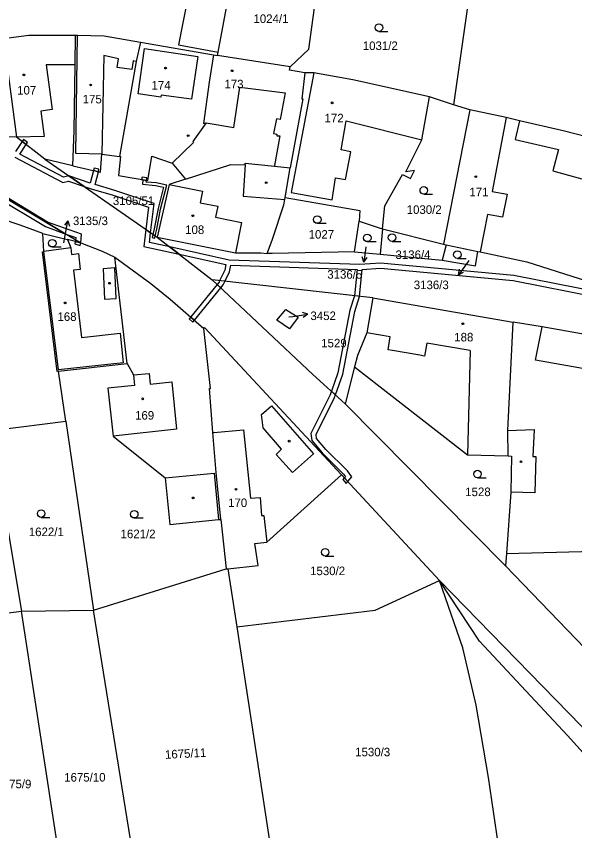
# Model space of a CAD drawing. Extents: x -776734 to -748832, y -1118122 to -976986.
# Drawn here: x -752860 to -752749.1, y -1115826.7 to -1115665 of the extents above; entities that cross this region are included whole.
import ezdxf

# ---------------------------------------------------------------- set-up
doc = ezdxf.new("R2010")
doc.units = 0
for name, color, linetype in [('KM_Hranice parcel', 7, 'Continuous'), ('KM_Parcelní čísla', 7, 'Continuous'), ('KM_Pop  PČ popisy', 7, 'Continuous'), ('KM_Vnitřní kresba', 7, 'Continuous'), ('KM_Věcná břemena k části', 7, 'Continuous'), ('KM_Značky budov', 7, 'Continuous'), ('KM_Značky kultur', 7, 'Continuous')]:
    doc.layers.add(name, color=color, linetype=linetype)

msp = doc.modelspace()

# ---------------------------------------------------------------- linework, layer by layer
at = {"layer": 'KM_Hranice parcel'}
for p, q in [((-752770.11, -1115661.14), (-752773.14, -1115682.57)), ((-752862.57, -1115669.36), (-752859.94, -1115688.99)), ((-752835.31, -1115670.11), (-752820.81, -1115672.62)), ((-752820.81, -1115672.62), (-752820.03, -1115672.75)), ((-752805.59, -1115675.01), (-752820.03, -1115672.75)), ((-752773.14, -1115682.57), (-752777.95, -1115680.94)), ((-752769.92, -1115683.54), (-752773.14, -1115682.57)), ((-752769.92, -1115683.54), (-752775.13, -1115710.23)), ((-752859.94, -1115688.99), (-752868.36, -1115688.71)), ((-752854.31, -1115693.32), (-752859.94, -1115688.99)), ((-752848.8, -1115694.67), (-752854.31, -1115693.32)), ((-752854.31, -1115693.32), (-752832.01, -1115708.85)), ((-752829.01, -1115694.11), (-752826.41, -1115697.32)), ((-752806.62, -1115700.96), (-752805.58, -1115695.03)), ((-752870.06, -1115696.32), (-752847.19, -1115709.96)), ((-752806.62, -1115700.96), (-752791.76, -1115703.53)), ((-752791.76, -1115703.53), (-752791.9, -1115705.62)), ((-752792.8, -1115711.7), (-752791.9, -1115705.62)), ((-752854.54, -1115711.68), (-752854.76, -1115708.06)), ((-752854.76, -1115708.06), (-752849.81, -1115709.31)), ((-752787.25, -1115707.18), (-752787.75, -1115712.18)), ((-752787.25, -1115707.18), (-752775.13, -1115710.23)), ((-752847.19, -1115709.96), (-752849.81, -1115709.31)), ((-752832.01, -1115708.85), (-752821.07, -1115717.32)), ((-752774.64, -1115710.33), (-752775.42, -1115713.37)), ((-752775.13, -1115710.23), (-752774.64, -1115710.33)), ((-752774.64, -1115710.33), (-752768.29, -1115711.67)), ((-752792.8, -1115711.7), (-752787.75, -1115712.18)), ((-752838, -1115733.9), (-752840.43, -1115712.78)), ((-752787.75, -1115712.18), (-752775.42, -1115713.37)), ((-752789.16, -1115720.89), (-752821.07, -1115717.32)), ((-752789.16, -1115720.89), (-752761.29, -1115725.71)), ((-752851.61, -1115735.44), (-752838, -1115733.9)), ((-752792.81, -1115734.59), (-752794.65, -1115741.88)), ((-752850.16, -1115745.33), (-752851.61, -1115735.44)), ((-752762.79, -1115774.11), (-752794.65, -1115741.88)), ((-752864.92, -1115747.25), (-752850.16, -1115745.33)), ((-752850.16, -1115745.33), (-752844.67, -1115782.9)), ((-752864.37, -1115751.01), (-752858.96, -1115783.05)), ((-752795.39, -1115755.98), (-752775.93, -1115776.97)), ((-752819.34, -1115764.85), (-752818.29, -1115774.68)), ((-752762.62, -1115771.65), (-752762.79, -1115774.11)), ((-752762.62, -1115771.65), (-752741.18, -1115771.07)), ((-752844.67, -1115782.9), (-752818.29, -1115774.68)), ((-752818.29, -1115774.68), (-752818, -1115774.65)), ((-752818, -1115774.65), (-752816.22, -1115786.21)), ((-752729.95, -1115808.28), (-752762.79, -1115774.11)), ((-752873.85, -1115785.05), (-752858.96, -1115783.05)), ((-752858.96, -1115783.05), (-752844.67, -1115782.9)), ((-752848.25, -1115852.83), (-752858.96, -1115783.05)), ((-752833.78, -1115850.14), (-752844.67, -1115782.9)), ((-752816.22, -1115786.21), (-752807.07, -1115845.79))]:
    msp.add_line(p, q, dxfattribs=at)
for points in [[(-752820.03, -1115672.75), (-752819.9, -1115672.08), (-752816.31, -1115652.88), (-752815.97, -1115650.74)], [(-752805.59, -1115675.01), (-752801.91, -1115671.5), (-752799.51, -1115654.01)], [(-752862.57, -1115669.36), (-752857.51, -1115668.7), (-752848.27, -1115668.68)], [(-752848.8, -1115694.67), (-752848.51, -1115687.63), (-752848.29, -1115674.57), (-752848.27, -1115668.68)], [(-752848.27, -1115668.68), (-752847.82, -1115668.69), (-752842.52, -1115668.84), (-752835.31, -1115670.11)], [(-752835.31, -1115670.11), (-752836.22, -1115673.92), (-752839.23, -1115691.3), (-752839.49, -1115692.79)], [(-752820.81, -1115672.62), (-752821.72, -1115678.02), (-752822.8, -1115686.25), (-752822.29, -1115686.12), (-752824.91, -1115689.79), (-752824.79, -1115690), (-752829.01, -1115694.11)], [(-752802.71, -1115676.22), (-752805.76, -1115675.67), (-752805.59, -1115675.01)], [(-752802.71, -1115676.22), (-752803.3, -1115681.33), (-752803.07, -1115681.37), (-752805.58, -1115695.03)], [(-752777.95, -1115680.94), (-752793.12, -1115677.57), (-752800.89, -1115676.17), (-752802.71, -1115676.22)], [(-752787.25, -1115707.18), (-752786.78, -1115702.59), (-752783.3, -1115696.36), (-752781.72, -1115697.14), (-752780.9, -1115695.57), (-752782.64, -1115695.83), (-752779.42, -1115689.51), (-752777.95, -1115680.94)], [(-752719.2, -1115696.43), (-752725.51, -1115694.41), (-752737.47, -1115691.3), (-752751.34, -1115687.73), (-752760.01, -1115685.71), (-752762.66, -1115685.09), (-752769.92, -1115683.54)], [(-752848.8, -1115694.67), (-752843.25, -1115695.92), (-752843.02, -1115692.33), (-752839.49, -1115692.79)], [(-752839.49, -1115692.79), (-752839.32, -1115692.81), (-752839.67, -1115696.59), (-752833.89, -1115697.59), (-752833.09, -1115692.74), (-752829.01, -1115694.11)], [(-752826.41, -1115697.32), (-752817.38, -1115694.37), (-752814.57, -1115694.44), (-752814.55, -1115694.14), (-752808.72, -1115694.72), (-752805.58, -1115695.03)], [(-752826.41, -1115697.32), (-752829.63, -1115698.33), (-752832.01, -1115708.85)], [(-752810.18, -1115712.03), (-752809.14, -1115709.22), (-752806.87, -1115702.43), (-752806.68, -1115701.33), (-752806.62, -1115700.96)], [(-752854.76, -1115708.06), (-752859.26, -1115706.43), (-752863.17, -1115705.14), (-752864.66, -1115704.88)], [(-752791.9, -1115705.62), (-752787.73, -1115707.05), (-752787.25, -1115707.18)], [(-752849.81, -1115709.31), (-752849.18, -1115710.96), (-752854.54, -1115711.68)], [(-752847.19, -1115709.96), (-752842.94, -1115711.59), (-752840.43, -1115712.78)], [(-752832.01, -1115708.85), (-752816.46, -1115711.91), (-752811.41, -1115711.95), (-752810.18, -1115712.03)], [(-752851.61, -1115735.44), (-752851.91, -1115735.47), (-752854.83, -1115711.72), (-752854.54, -1115711.68)], [(-752792.8, -1115711.7), (-752809.19, -1115712.09), (-752810.18, -1115712.03)], [(-752775.42, -1115713.37), (-752768.78, -1115714.51), (-752768.29, -1115711.67)], [(-752768.29, -1115711.67), (-752767.84, -1115711.76), (-752758.58, -1115713.72), (-752746.7, -1115717.52), (-752736.61, -1115720.55), (-752727.86, -1115722.24)], [(-752840.43, -1115712.78), (-752833.26, -1115718), (-752829.45, -1115721.1), (-752822.74, -1115726.96)], [(-752794.65, -1115741.88), (-752801.11, -1115736.06), (-752821.07, -1115717.32)], [(-752789.16, -1115720.89), (-752790.38, -1115727.84), (-752792.23, -1115732.29), (-752792.81, -1115734.59)], [(-752806.46, -1115723.16), (-752804, -1115724.71), (-752805.7, -1115727.03), (-752808.22, -1115725.31), (-752806.46, -1115723.16)], [(-752762.28, -1115752.26), (-752762.35, -1115747.19), (-752761.29, -1115725.71)], [(-752732.48, -1115730.75), (-752755.56, -1115726.65), (-752761.29, -1115725.71)], [(-752822.74, -1115726.96), (-752822.62, -1115726.73), (-752795.39, -1115755.98)], [(-752819.34, -1115764.85), (-752820.33, -1115755.58), (-752820.95, -1115747.63), (-752821.63, -1115738.88), (-752821.44, -1115738.86), (-752822.74, -1115726.96)], [(-752838, -1115733.9), (-752836.75, -1115736.17), (-752836.54, -1115738.29), (-752841.83, -1115738.81), (-752840.78, -1115748.33), (-752830.42, -1115756.6), (-752829.53, -1115765.85), (-752819.83, -1115764.9), (-752819.34, -1115764.85)], [(-752792.81, -1115734.59), (-752770.36, -1115752.06), (-752762.28, -1115752.26)], [(-752762.28, -1115752.26), (-752761.66, -1115752.28), (-752761.77, -1115759.47), (-752762.62, -1115771.65)], [(-752818, -1115774.65), (-752811.98, -1115774.01), (-752812.59, -1115769.65), (-752810.26, -1115769.4), (-752795.39, -1115755.98)], [(-752816.22, -1115786.21), (-752788.74, -1115782.85), (-752775.93, -1115776.97)], [(-752736.32, -1115823.45), (-752750.53, -1115807.77), (-752767.96, -1115789.02), (-752775.93, -1115776.97)], [(-752762.91, -1115838.6), (-752766.17, -1115816.08), (-752768.64, -1115801.76), (-752771.29, -1115790.38), (-752775.93, -1115776.97)], [(-752775.93, -1115776.97), (-752724.69, -1115829.55), (-752661.99, -1115897.03)]]:
    msp.add_lwpolyline(points, dxfattribs=at)
at = {"layer": 'KM_Pop  PČ popisy'}
for p, q in [((-752849.779, -1115705.565), (-752850.446, -1115706.464)), ((-752850.3, -1115708.52), (-752849.779, -1115705.565)), ((-752849.779, -1115705.565), (-752849.46, -1115706.638)), ((-752850.56, -1115709.95), (-752850.3, -1115708.52)), ((-752790.57, -1115710.83), (-752790.936, -1115713.809)), ((-752790.56, -1115710.75), (-752790.57, -1115710.83)), ((-752790.936, -1115713.809), (-752791.311, -1115712.754)), ((-752790.936, -1115713.809), (-752790.317, -1115712.876)), ((-752770.08, -1115713.46), (-752770.38, -1115713.87)), ((-752770.38, -1115713.87), (-752772.144, -1115716.298)), ((-752772.144, -1115716.298), (-752771.96, -1115715.193)), ((-752772.144, -1115716.298), (-752771.15, -1115715.782)), ((-752805.89, -1115724.67), (-752805.09, -1115724.55)), ((-752805.09, -1115724.55), (-752802.118, -1115724.132)), ((-752802.118, -1115724.132), (-752803.18, -1115723.776)), ((-752802.118, -1115724.132), (-752803.04, -1115724.768))]:
    msp.add_line(p, q, dxfattribs=at)
at = {"layer": 'KM_Vnitřní kresba'}
for p, q in [((-752824.01, -1115651.39), (-752827.78, -1115670.61)), ((-752848.15, -1115692.22), (-752847.82, -1115668.69)), ((-752835.82, -1115680.38), (-752834.51, -1115671.36)), ((-752834.51, -1115671.36), (-752823.92, -1115672.93)), ((-752827.78, -1115670.61), (-752819.9, -1115672.08)), ((-752842.62, -1115672.72), (-752843.02, -1115692.33)), ((-752839.71, -1115673.39), (-752842.62, -1115672.72)), ((-752823.92, -1115672.93), (-752825.18, -1115681.43)), ((-752848.29, -1115674.57), (-752854.09, -1115674.63)), ((-752854.09, -1115674.63), (-752852.91, -1115683.48)), ((-752839.96, -1115675.11), (-752839.71, -1115673.39)), ((-752836.81, -1115673.83), (-752837.06, -1115675.53)), ((-752836.22, -1115673.92), (-752836.81, -1115673.83)), ((-752837.06, -1115675.53), (-752839.96, -1115675.11)), ((-752800.89, -1115676.17), (-752805.4, -1115699.93)), ((-752816.79, -1115687.06), (-752815.61, -1115679.02)), ((-752815.61, -1115679.02), (-752806.62, -1115680.14)), ((-752831.31, -1115681.04), (-752835.82, -1115680.38)), ((-752831.24, -1115680.59), (-752831.31, -1115681.04)), ((-752825.18, -1115681.43), (-752831.24, -1115680.59)), ((-752806.62, -1115680.14), (-752807.58, -1115685.45)), ((-752852.91, -1115683.48), (-752855.15, -1115683.78)), ((-752855.15, -1115683.78), (-752854.49, -1115688.86)), ((-752808.32, -1115685.3), (-752808.92, -1115688.24)), ((-752807.58, -1115685.45), (-752808.32, -1115685.3)), ((-752795.44, -1115691.49), (-752794.48, -1115685.73)), ((-752794.48, -1115685.73), (-752779.42, -1115689.51)), ((-752762.66, -1115685.09), (-752765.5, -1115699.72)), ((-752760.01, -1115685.71), (-752760.88, -1115689.45)), ((-752822.29, -1115686.12), (-752816.79, -1115687.06)), ((-752854.49, -1115688.86), (-752859.94, -1115688.99)), ((-752808.92, -1115688.24), (-752808.25, -1115688.38)), ((-752807.65, -1115688.71), (-752808.7, -1115694.59)), ((-752808.25, -1115688.38), (-752808.26, -1115688.7)), ((-752808.26, -1115688.7), (-752807.65, -1115688.71)), ((-752760.88, -1115689.45), (-752752.3, -1115691.44)), ((-752843.02, -1115692.33), (-752848.15, -1115692.22)), ((-752793.53, -1115691.86), (-752795.44, -1115691.49)), ((-752794.6, -1115697.4), (-752793.53, -1115691.86)), ((-752752.3, -1115691.44), (-752753.39, -1115695.67)), ((-752814.57, -1115694.44), (-752814.95, -1115700.71)), ((-752808.7, -1115694.59), (-752808.72, -1115694.72)), ((-752753.39, -1115695.67), (-752739.48, -1115699.47)), ((-752797.27, -1115701.43), (-752796.57, -1115697.03)), ((-752796.57, -1115697.03), (-752794.6, -1115697.4)), ((-752829.63, -1115698.33), (-752823.01, -1115699.68)), ((-752823.01, -1115699.68), (-752823.48, -1115701.98)), ((-752805.4, -1115699.93), (-752797.27, -1115701.43)), ((-752765.5, -1115699.72), (-752762.52, -1115700.3)), ((-752762.52, -1115700.3), (-752763.41, -1115704.87)), ((-752823.48, -1115701.98), (-752820, -1115702.64)), ((-752814.95, -1115700.71), (-752806.68, -1115701.33)), ((-752820, -1115702.64), (-752820.42, -1115704.88)), ((-752820.42, -1115704.88), (-752815.29, -1115705.89)), ((-752766.39, -1115704.29), (-752767.84, -1115711.76)), ((-752763.41, -1115704.87), (-752766.39, -1115704.29)), ((-752815.29, -1115705.89), (-752816.46, -1115711.91)), ((-752851.65, -1115735.14), (-752854.54, -1115711.68)), ((-752849.18, -1115710.96), (-752849.02, -1115712.25)), ((-752849.02, -1115712.25), (-752847.62, -1115712.08)), ((-752847.62, -1115712.08), (-752847.3, -1115715.24)), ((-752840.42, -1115714.92), (-752842.76, -1115715.09)), ((-752842.76, -1115715.09), (-752842.5, -1115721.12)), ((-752840.14, -1115720.98), (-752840.42, -1115714.92)), ((-752847.3, -1115715.24), (-752848.64, -1115715.4)), ((-752848.64, -1115715.4), (-752847.03, -1115728.75)), ((-752842.5, -1115721.12), (-752840.14, -1115720.98)), ((-752847.03, -1115728.75), (-752839.39, -1115727.9)), ((-752839.39, -1115727.9), (-752838.77, -1115733.74)), ((-752785.72, -1115728.64), (-752790.38, -1115727.84)), ((-752756.83, -1115733.24), (-752755.56, -1115726.65)), ((-752786.16, -1115731.19), (-752785.72, -1115728.64)), ((-752785.26, -1115731.34), (-752786.16, -1115731.19)), ((-752779.83, -1115732.27), (-752785.26, -1115731.34)), ((-752778.46, -1115729.88), (-752778.9, -1115732.43)), ((-752769.84, -1115731.35), (-752778.46, -1115729.88)), ((-752769.84, -1115731.35), (-752770.36, -1115752.06)), ((-752778.9, -1115732.43), (-752779.83, -1115732.27)), ((-752838.77, -1115733.74), (-752851.65, -1115735.14)), ((-752740.98, -1115736.06), (-752756.83, -1115733.24)), ((-752836.75, -1115736.17), (-752833.63, -1115735.86)), ((-752833.63, -1115735.86), (-752833.42, -1115737.99)), ((-752833.42, -1115737.99), (-752829.13, -1115737.57)), ((-752829.13, -1115737.57), (-752828.2, -1115746.94)), ((-752811.27, -1115744.06), (-752809.29, -1115742.33)), ((-752809.29, -1115742.33), (-752800.96, -1115751.81)), ((-752810.96, -1115746.66), (-752811.27, -1115744.06)), ((-752828.2, -1115746.94), (-752840.78, -1115748.33)), ((-752820.75, -1115747.61), (-752814.85, -1115747.08)), ((-752814.85, -1115747.08), (-752813.46, -1115760.66)), ((-752807.3, -1115750.89), (-752810.96, -1115746.66)), ((-752762.35, -1115747.19), (-752757.1, -1115747)), ((-752757.1, -1115747), (-752757.38, -1115752.35)), ((-752820.95, -1115747.63), (-752820.75, -1115747.61)), ((-752808.39, -1115751.96), (-752807.3, -1115750.89)), ((-752805.16, -1115755.57), (-752808.39, -1115751.96)), ((-752800.96, -1115751.81), (-752805.16, -1115755.57)), ((-752757.38, -1115752.35), (-752756.82, -1115752.36)), ((-752756.82, -1115752.36), (-752756.99, -1115759.57)), ((-752830.42, -1115756.6), (-752820.72, -1115755.67)), ((-752820.72, -1115755.67), (-752819.83, -1115764.9)), ((-752756.99, -1115759.57), (-752761.77, -1115759.47)), ((-752813.46, -1115760.66), (-752811.55, -1115760.51)), ((-752811.55, -1115760.51), (-752811.27, -1115764.1)), ((-752811.27, -1115764.1), (-752810.82, -1115764.06)), ((-752810.82, -1115764.06), (-752810.26, -1115769.4))]:
    msp.add_line(p, q, dxfattribs=at)
at = {"layer": 'KM_Věcná břemena k části'}
for points in [[(-752860.3, -1115692.93), (-752850.76, -1115697.99), (-752849.66, -1115697.69), (-752846.51, -1115698.75), (-752849.55, -1115696.63), (-752850.66, -1115696.91), (-752859.32, -1115692.31), (-752858.05, -1115690.45), (-752858.83, -1115689.84), (-752860.18, -1115691.81)], [(-752864.5, -1115699.64), (-752850.16, -1115708.19), (-752848.17, -1115708.91), (-752848.25, -1115709.33), (-752847.19, -1115709.96), (-752847.05, -1115708.25), (-752853.81, -1115705.81), (-752863.57, -1115699.98)], [(-752863.98, -1115700.9), (-752854.23, -1115706.71), (-752850.16, -1115708.19), (-752864.5, -1115699.64)], [(-752744.32, -1115719.75), (-752761.17, -1115716.41), (-752787.62, -1115713.98), (-752791.75, -1115714.26), (-752817.75, -1115713.38), (-752829.53, -1115710.77), (-752827.67, -1115712.21), (-752818.4, -1115714.27), (-752818.59, -1115715.37), (-752819.61, -1115717.48), (-752819.73, -1115717.73), (-752820.12, -1115718.21), (-752819.39, -1115718.9), (-752818.88, -1115718.27), (-752818.56, -1115717.6), (-752817.63, -1115715.69), (-752817.4, -1115714.4), (-752792.29, -1115715.24), (-752792.82, -1115720.48), (-752793.74, -1115723.33), (-752796.13, -1115735.73), (-752797.42, -1115739.38), (-752796.62, -1115740.11), (-752795.16, -1115736), (-752792.77, -1115723.58), (-752791.81, -1115720.59), (-752791.28, -1115715.23), (-752787.64, -1115714.98), (-752761.3, -1115717.4), (-752744.56, -1115720.72)]]:
    msp.add_lwpolyline(points, dxfattribs=at)
for points in [[(-752858.83, -1115689.84), (-752858.05, -1115690.45), (-752857.77, -1115690.04), (-752858.55, -1115689.43)], [(-752840.76, -1115700.48), (-752833.74, -1115702.83), (-752834.26, -1115707.28), (-752833.33, -1115707.93), (-752832.65, -1115702.14), (-752840.45, -1115699.53), (-752844.36, -1115698.39), (-752843.7, -1115695.82), (-752844.68, -1115695.6), (-752845.32, -1115698.09), (-752849.55, -1115696.63), (-752846.51, -1115698.75), (-752845.12, -1115699.22)], [(-752844.68, -1115695.6), (-752843.7, -1115695.82), (-752843.58, -1115695.34), (-752844.56, -1115695.12)], [(-752834.87, -1115697.42), (-752834.13, -1115697.55), (-752834.05, -1115697.06), (-752835.03, -1115696.88), (-752835.12, -1115697.38)], [(-752834.13, -1115697.55), (-752834.87, -1115697.42), (-752834.94, -1115698.32), (-752832.32, -1115698.56), (-752830.74, -1115698.86), (-752831.81, -1115703.15), (-752832.59, -1115707.14), (-752832.85, -1115708.27), (-752832.41, -1115708.57), (-752832.11, -1115707.24), (-752831.33, -1115703.25), (-752830.12, -1115698.48), (-752832.24, -1115698.06), (-752834.19, -1115697.88)], [(-752834.26, -1115707.28), (-752834.66, -1115710.66), (-752827.67, -1115712.21), (-752829.53, -1115710.77), (-752833.56, -1115709.88), (-752833.33, -1115707.93)], [(-752832.41, -1115708.57), (-752832.85, -1115708.27), (-752832.99, -1115708.88), (-752832.5, -1115708.99)], [(-752847.31, -1115710.45), (-752847.19, -1115709.96), (-752848.31, -1115709.68), (-752848.4, -1115710.17)], [(-752848.25, -1115709.33), (-752848.31, -1115709.68), (-752847.19, -1115709.96)], [(-752824.61, -1115725.32), (-752819.39, -1115718.9), (-752820.12, -1115718.21), (-752825.36, -1115724.67)], [(-752824.61, -1115725.32), (-752825.36, -1115724.67), (-752825.68, -1115725.06), (-752824.93, -1115725.71)], [(-752796.62, -1115740.11), (-752797.42, -1115739.38), (-752797.74, -1115740.29), (-752801.47, -1115747.79), (-752801.3, -1115749.22), (-752799.23, -1115751.66), (-752794.99, -1115755.89), (-752794.6, -1115756.39), (-752794.79, -1115756.63), (-752794.11, -1115757.36), (-752793.34, -1115756.39), (-752794.24, -1115755.22), (-752798.5, -1115750.97), (-752800.34, -1115748.8), (-752800.45, -1115747.97), (-752796.82, -1115740.68)], [(-752794.11, -1115757.36), (-752794.79, -1115756.63), (-752795.16, -1115756.97), (-752794.48, -1115757.7)]]:
    msp.add_lwpolyline(points, close=True, dxfattribs=at)
at = {"layer": 'KM_Značky budov'}
for centre in [(-752830.3468, -1115675.2392), (-752817.1368, -1115675.7792), (-752858.5068, -1115676.6092), (-752845.2368, -1115678.5992), (-752797.2668, -1115682.1492), (-752825.8668, -1115688.6692), (-752768.7368, -1115696.7992), (-752810.3568, -1115697.9892), (-752824.9268, -1115704.5692), (-752841.4668, -1115717.9692), (-752850.3068, -1115721.8692), (-752771.2968, -1115726.0092), (-752834.9068, -1115740.9192), (-752805.7868, -1115749.3292), (-752759.7368, -1115753.4192), (-752816.3568, -1115758.8792), (-752824.8768, -1115760.5892)]:
    msp.add_circle(centre, 0.175, dxfattribs=at)
at = {"layer": 'KM_Značky kultur'}
for p, q in [((-752787.953, -1115667.95), (-752786.203, -1115667.95)), ((-752779.053, -1115700.28), (-752777.303, -1115700.28)), ((-752800.213, -1115706.07), (-752798.463, -1115706.07)), ((-752790.283, -1115709.71), (-752788.533, -1115709.71)), ((-752785.353, -1115709.65), (-752783.603, -1115709.65)), ((-752852.863, -1115710.77), (-752851.113, -1115710.77)), ((-752772.383, -1115713.04), (-752770.633, -1115713.04)), ((-752768.383, -1115756.61), (-752766.633, -1115756.61)), ((-752855.063, -1115764.46), (-752853.313, -1115764.46)), ((-752836.583, -1115764.58), (-752834.833, -1115764.58)), ((-752798.643, -1115772.13), (-752796.893, -1115772.13))]:
    msp.add_line(p, q, dxfattribs=at)
for centre in [(-752787.9529, -1115667.1998), (-752779.0529, -1115699.5298), (-752800.2129, -1115705.3198), (-752790.2829, -1115708.9598), (-752785.3529, -1115708.8998), (-752852.8629, -1115710.0198), (-752772.3829, -1115712.2898), (-752768.3829, -1115755.8598), (-752855.0629, -1115763.7098), (-752836.5829, -1115763.8298), (-752798.6429, -1115771.3798)]:
    msp.add_circle(centre, 0.75, dxfattribs=at)

# ---------------------------------------------------------------- texts
at = {"layer": 'KM_Parcelní čísla'}
for s, p in [('1024/1', (-752812.89, -1115666.29)), ('1031/2', (-752791.17, -1115671.66)), ('174', (-752833.14, -1115679.5)), ('173', (-752818.66, -1115679.27)), ('107', (-752859.84, -1115680.5)), ('175', (-752846.82, -1115682.26)), ('172', (-752798.77, -1115686.02)), ('171', (-752770, -1115700.71)), ('3105/51', (-752840.82, -1115702.44)), ('1030/2', (-752782.45, -1115704.2)), ('3135/3', (-752848.76, -1115706.42)), ('108', (-752826.46, -1115708.19)), ('1027', (-752801.93, -1115709.12)), ('3136/4', (-752784.67, -1115713.15)), ('3136/5', (-752798.225, -1115717.068)), ('3136/3', (-752781.045, -1115719.138)), ('168', (-752851.83, -1115725.45)), ('3452', (-752801.574, -1115725.28)), ('188', (-752773, -1115729.52)), ('1529', (-752799.43, -1115730.71)), ('169', (-752836.41, -1115745.05)), ('1528', (-752770.82, -1115760.24)), ('170', (-752817.93, -1115762.41)), ('1622/1', (-752857.52, -1115768.18)), ('1621/2', (-752839.29, -1115768.59)), ('1530/2', (-752801.64, -1115775.93)), ('1530/3', (-752792.68, -1115811.9)), ('1675/10', (-752850.49, -1115816.92)), ('1675/9', (-752863.96, -1115818.25))]:
    msp.add_text(s, height=1.7, dxfattribs=at).set_placement(p)
msp.add_text('1675/11', height=1.7, rotation=3, dxfattribs=at).set_placement((-752830.425, -1115812.418))

doc.saveas('drawing.dxf')
